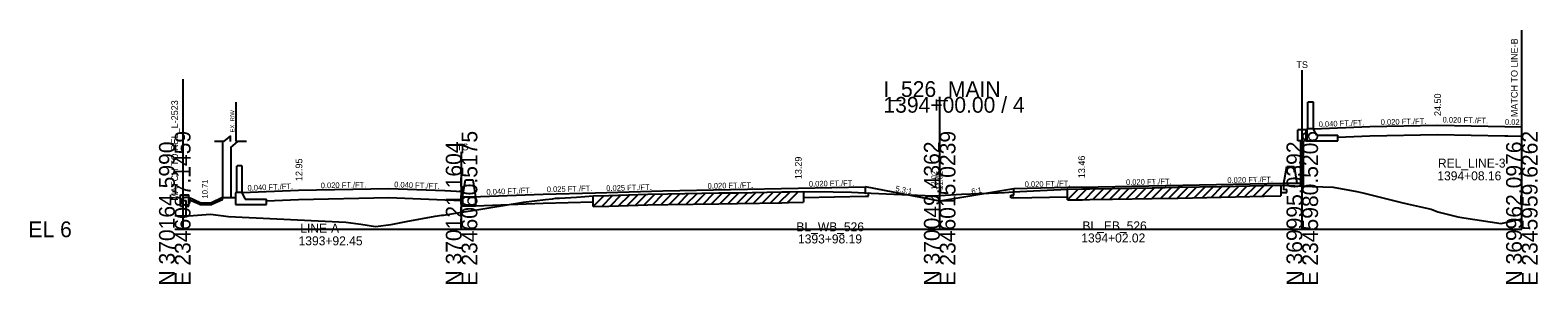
# Model space of a CAD drawing. Extents: x -170 to 2527928, y -10 to 1619750.
# Drawn here: x 1974.3 to 2242.2, y 5990.3 to 6035.4 of the extents above; entities that cross this region are included whole.
import ezdxf

# ---------------------------------------------------------------- set-up
doc = ezdxf.new("R2010")
doc.units = 0
for name, color, linetype in [('Default', 7, 'Continuous'), ('RD_GPK_XS_Cell', 7, 'Continuous'), ('RD_PD_NOISE-WALL-GM', 7, 'Continuous'), ('RD_PD_WallFill', 7, 'Continuous'), ('RD_XS_Base', 7, 'Continuous'), ('RD_XS_EarthShd', 7, 'Continuous'), ('RD_XS_ExGround', 7, 'Continuous'), ('RD_XS_ExPaveRet', 7, 'Continuous'), ('RD_XS_ExRW', 7, 'Continuous'), ('RD_XS_MatchLine', 7, 'Continuous'), ('RD_XS_MedBWall', 7, 'Continuous'), ('RD_XS_Pave', 7, 'Continuous'), ('RD_XS_PaveShd', 7, 'Continuous'), ('RD_XS_TieSlope', 7, 'Continuous'), ('RD_XS_TX_Elev_EX', 7, 'Continuous'), ('RD_XS_TX_Elev_PR', 7, 'Continuous'), ('RD_XS_TX_Slope', 7, 'Continuous'), ('RD_XS_TX_Station', 7, 'Continuous')]:
    doc.layers.add(name, color=color, linetype=linetype)

msp = doc.modelspace()

# ---------------------------------------------------------------- linework, layer by layer
at = {"layer": 'Default'}
for p, q in [((2009.88, 6016.61), (2008.63, 6015.58)), ((2009.88, 6015.58), (2009.88, 6016.61)), ((2008.63, 6015.58), (2007.05, 6015.58)), ((2011.13, 6015.58), (2009.88, 6014.55)), ((2012.72, 6015.58), (2011.13, 6015.58))]:
    msp.add_line(p, q, dxfattribs=at)
at = {"layer": 'RD_GPK_XS_Cell'}
for p, q in [((2135.89, 6000), (2135.89, 6023.52)), ((2000, 6000), (2050.95, 6000)), ((2050.95, 6000), (2135.89, 6000)), ((2135.89, 6000), (2200.3, 6000)), ((2200.3, 6000), (2239.31, 6000))]:
    msp.add_line(p, q, dxfattribs=at)
at = {"layer": 'RD_PD_NOISE-WALL-GM'}
for p, q in [((2008.5, 6015.58), (2008.5, 6005.63)), ((2010, 6005.63), (2010, 6014.66)), ((2197.05, 6008.18), (2197.53, 6011.18)), ((2197.53, 6011.18), (2198.87, 6011.18)), ((2198.87, 6011.18), (2199.36, 6008.18)), ((2051.14, 6005.79), (2051.62, 6008.79)), ((2051.62, 6008.79), (2052.96, 6008.79)), ((2052.96, 6008.79), (2053.45, 6005.79)), ((2051.14, 6005.79), (2053.45, 6005.79))]:
    msp.add_line(p, q, dxfattribs=at)
at = {"layer": 'RD_PD_WallFill'}
for p, q in [((2201.3, 6017.86), (2201.3, 6022.62)), ((2202.3, 6022.62), (2201.3, 6022.62)), ((2202.3, 6017.86), (2202.3, 6022.62)), ((2199.52, 6015.7), (2199.52, 6017.7)), ((2201.02, 6017.7), (2199.52, 6017.7)), ((2201.17, 6017.86), (2201.01, 6017.7)), ((2201.02, 6015.7), (2201.02, 6017.7)), ((2201.09, 6017.7), (2201.02, 6017.7)), ((2201.09, 6017.78), (2201.09, 6015.7)), ((2202.3, 6017.86), (2201.17, 6017.86)), ((2202.3, 6017.86), (2202.3, 6017.7)), ((2202.3, 6017.7), (2202.8, 6016.7)), ((2202.8, 6016.7), (2206.59, 6016.7)), ((2206.59, 6015.7), (2206.59, 6016.7)), ((2239.31, 6001.87), (2239.31, 6018.2)), ((2200.02, 6015.7), (2199.52, 6015.7)), ((2200.02, 6007.7), (2200.02, 6015.7)), ((2200.52, 6007.68), (2200.52, 6015.7)), ((2201.02, 6015.7), (2200.52, 6015.7)), ((2201.02, 6015.7), (2206.59, 6015.7)), ((2201.09, 6015.7), (2201.02, 6015.7)), ((2011.08, 6011.3), (2011, 6011.22)), ((2011, 6006.55), (2011, 6011.22)), ((2011.92, 6011.3), (2011.08, 6011.3)), ((2011.92, 6011.3), (2012, 6011.22)), ((2012, 6006.55), (2012, 6011.22)), ((2197.05, 6008.18), (2200.02, 6008.18)), ((2001, 6006.13), (2002.5, 6006.13)), ((2001, 6004.13), (2001, 6006.13)), ((2001.5, 6002.43), (2001.5, 6005.13)), ((2001.5, 6005.13), (2002, 6005.13)), ((2002, 6002.38), (2002, 6005.13)), ((2002.5, 6004.13), (2002.5, 6006.13)), ((2004.5, 6004.71), (2002.5, 6005.63)), ((2004.43, 6004.38), (2002.5, 6005.26)), ((2008.5, 6005.63), (2006.5, 6004.71)), ((2008.5, 6005.26), (2006.57, 6004.38)), ((2008.5, 6005.26), (2008.5, 6005.63)), ((2010.87, 6006.55), (2010.79, 6006.47)), ((2010.79, 6006.47), (2010.79, 6004.38)), ((2012, 6006.55), (2010.87, 6006.55)), ((2012, 6006.55), (2012, 6006.38)), ((2012, 6006.38), (2012.49, 6005.38)), ((2012.49, 6005.38), (2016.29, 6005.38)), ((2016.29, 6004.38), (2016.29, 6005.38)), ((2051.11, 6006.74), (2051.11, 6005.7)), ((2001, 6004.13), (2001.5, 6004.13)), ((2002, 6004.13), (2002.5, 6004.13)), ((2004.43, 6004.38), (2006.57, 6004.38)), ((2004.5, 6004.71), (2006.5, 6004.71)), ((2010.79, 6004.38), (2016.29, 6004.38))]:
    msp.add_line(p, q, dxfattribs=at)
at = {"layer": 'RD_XS_Base'}
for p, q in [((2206.59, 6016.4), (2212.3, 6016.63)), ((2212.3, 6016.63), (2224.3, 6016.87)), ((2224.3, 6016.87), (2236.3, 6016.63)), ((2236.3, 6016.63), (2236.8, 6016.62)), ((2236.3, 6016.63), (2239.31, 6016.57)), ((2197.05, 6007.04), (2197.05, 6008.18)), ((2016.29, 6005.08), (2022, 6005.31)), ((2022, 6005.31), (2038, 6005.63)), ((2038, 6005.63), (2048, 6005.23)), ((2048, 6005.23), (2051.11, 6005.11)), ((2051.11, 6005.11), (2051.11, 6006.15)), ((2111.68, 6005.67), (2122.72, 6005.89)), ((2122.72, 6006.39), (2122.72, 6007.53)), ((2123.22, 6006.4), (2122.72, 6006.39)), ((2122.72, 6005.89), (2123.22, 6005.9)), ((2123.22, 6005.9), (2123.22, 6006.4)), ((2148.55, 6006.07), (2149.05, 6006.08)), ((2148.55, 6005.57), (2148.55, 6006.07)), ((2149.05, 6005.58), (2148.55, 6005.57)), ((2149.05, 6006.08), (2149.05, 6007.22)), ((2149.05, 6005.58), (2158.59, 6005.77)), ((2196.48, 6006.53), (2197.05, 6006.54)), ((2197.55, 6007.05), (2197.05, 6007.04)), ((2197.05, 6006.54), (2197.55, 6006.55)), ((2197.55, 6006.55), (2197.55, 6007.05)), ((2053.45, 6004.16), (2065.45, 6004.64)), ((2065.45, 6004.64), (2074.34, 6004.86))]:
    msp.add_line(p, q, dxfattribs=at)
at = {"layer": 'RD_XS_EarthShd'}
msp.add_line((2008.5, 6005.63), (2010.79, 6005.63), dxfattribs=at)
at = {"layer": 'RD_XS_ExGround'}
msp.add_lwpolyline([(2000, 6002.44), (2002.5, 6002.41), (2006.37, 6002.69), (2009.53, 6002.26), (2030.38, 6001.26), (2033.05, 6000.92), (2035.68, 6000.51), (2038.44, 6000.84), (2041.11, 6001.36), (2046.26, 6002.31), (2047.42, 6002.5), (2047.71, 6002.5), (2050.95, 6003.03), (2051.75, 6003.16), (2054, 6003.5), (2055.77, 6003.79), (2061.96, 6004.85), (2065.87, 6005.27), (2067.11, 6005.42), (2067.63, 6005.51), (2068.36, 6005.53), (2071.39, 6005.73), (2074.34, 6005.95), (2077.13, 6006.03), (2084.01, 6006.25), (2087.58, 6006.31), (2096.65, 6006.46), (2099.95, 6006.51), (2107.85, 6006.65), (2109, 6006.67), (2111.68, 6006.73), (2116.97, 6006.65), (2120.21, 6006.62), (2123.71, 6006.45), (2127.72, 6006.26), (2134.73, 6005.96), (2135.89, 6006.02), (2139.78, 6006.23), (2146.29, 6006.49), (2147.43, 6006.55), (2148.95, 6006.63), (2158.59, 6007.16), (2161.27, 6007.18), (2162.59, 6007.19), (2166.61, 6007.27), (2173.62, 6007.38), (2178.24, 6007.47), (2185.91, 6007.63), (2193.51, 6007.78), (2196.48, 6007.84), (2197.71, 6007.79), (2200.3, 6007.69), (2205.8, 6007.46), (2209.98, 6006.7), (2211.07, 6006.49), (2217.69, 6004.81), (2218.92, 6004.5), (2218.94, 6004.5), (2223.2, 6003.55), (2224.41, 6003.1), (2227.94, 6002.21), (2228.98, 6002.03), (2235.63, 6001.02), (2239.31, 6001.87)], dxfattribs=at)
at = {"layer": 'RD_XS_ExPaveRet'}
for p, q in [((2191.59, 6005.82), (2193.54, 6007.78)), ((2193.09, 6005.85), (2195.05, 6007.81)), ((2196.48, 6007.84), (2196.48, 6005.92)), ((2074.34, 6004.04), (2076.31, 6006.01)), ((2074.34, 6004.04), (2074.34, 6005.95)), ((2075.84, 6004.08), (2077.81, 6006.05)), ((2077.34, 6004.12), (2079.32, 6006.1)), ((2078.84, 6004.17), (2080.82, 6006.15)), ((2080.34, 6004.22), (2082.32, 6006.19)), ((2081.84, 6004.26), (2083.82, 6006.24)), ((2083.34, 6004.31), (2085.3, 6006.27)), ((2084.84, 6004.34), (2086.79, 6006.29)), ((2086.34, 6004.37), (2088.29, 6006.32)), ((2087.84, 6004.4), (2089.79, 6006.34)), ((2089.34, 6004.42), (2091.29, 6006.37)), ((2090.84, 6004.44), (2092.79, 6006.39)), ((2092.34, 6004.47), (2094.29, 6006.42)), ((2093.84, 6004.49), (2095.79, 6006.44)), ((2095.34, 6004.52), (2097.29, 6006.47)), ((2096.84, 6004.54), (2098.79, 6006.49)), ((2098.34, 6004.57), (2100.29, 6006.52)), ((2099.84, 6004.59), (2101.79, 6006.54)), ((2101.34, 6004.62), (2103.29, 6006.57)), ((2102.84, 6004.64), (2104.79, 6006.59)), ((2104.34, 6004.67), (2106.29, 6006.62)), ((2105.84, 6004.69), (2107.79, 6006.64)), ((2107.34, 6004.72), (2109.3, 6006.68)), ((2108.84, 6004.75), (2110.8, 6006.71)), ((2111.68, 6006.73), (2111.68, 6004.81)), ((2158.59, 6005.24), (2160.52, 6007.17)), ((2158.59, 6005.24), (2158.59, 6007.16)), ((2158.59, 6005.24), (2161.27, 6005.26)), ((2160.09, 6005.25), (2162.02, 6007.19)), ((2161.27, 6005.26), (2162.59, 6005.27)), ((2161.59, 6005.26), (2163.53, 6007.21)), ((2162.59, 6005.27), (2166.61, 6005.35)), ((2163.09, 6005.28), (2165.04, 6007.24)), ((2164.59, 6005.31), (2166.54, 6007.27)), ((2166.09, 6005.34), (2168.04, 6007.29)), ((2166.61, 6005.35), (2173.62, 6005.46)), ((2167.59, 6005.37), (2169.54, 6007.31)), ((2169.09, 6005.39), (2171.04, 6007.34)), ((2170.59, 6005.41), (2172.54, 6007.36)), ((2172.09, 6005.44), (2174.04, 6007.39)), ((2173.59, 6005.46), (2175.54, 6007.42)), ((2173.62, 6005.46), (2178.24, 6005.55)), ((2175.09, 6005.49), (2177.05, 6007.45)), ((2176.59, 6005.52), (2178.55, 6007.48)), ((2178.09, 6005.55), (2180.05, 6007.51)), ((2178.24, 6005.55), (2185.91, 6005.72)), ((2179.59, 6005.58), (2181.55, 6007.54)), ((2181.09, 6005.61), (2183.05, 6007.57)), ((2182.59, 6005.65), (2184.55, 6007.6)), ((2184.09, 6005.68), (2186.05, 6007.64)), ((2185.59, 6005.71), (2187.54, 6007.66)), ((2185.91, 6005.72), (2193.51, 6005.86)), ((2187.09, 6005.74), (2189.04, 6007.69)), ((2188.59, 6005.77), (2190.54, 6007.72)), ((2190.09, 6005.8), (2192.04, 6007.75)), ((2193.51, 6005.86), (2196.48, 6005.92)), ((2074.34, 6004.04), (2077.13, 6004.12)), ((2077.13, 6004.12), (2084.01, 6004.33)), ((2084.01, 6004.33), (2087.58, 6004.39)), ((2087.58, 6004.39), (2096.65, 6004.54)), ((2096.65, 6004.54), (2099.95, 6004.6)), ((2099.95, 6004.6), (2107.85, 6004.73)), ((2107.85, 6004.73), (2109, 6004.75)), ((2109, 6004.75), (2111.68, 6004.81))]:
    msp.add_line(p, q, dxfattribs=at)
at = {"layer": 'RD_XS_ExRW'}
msp.add_line((2010.88, 6015.6), (2010.88, 6022.6), dxfattribs=at)
at = {"layer": 'RD_XS_MatchLine'}
for p, q in [((2239.31, 6000), (2239.31, 6035.39)), ((2001.5, 6000), (2001.5, 6026.65)), ((2200.3, 6000), (2200.3, 6028.27)), ((2050.95, 6000), (2050.95, 6013.78))]:
    msp.add_line(p, q, dxfattribs=at)
at = {"layer": 'RD_XS_MedBWall'}
for p, q in [((2051.11, 6005.79), (2051.11, 6004.16)), ((2053.45, 6005.79), (2053.45, 6004.16)), ((2051.11, 6004.16), (2053.45, 6004.16))]:
    msp.add_line(p, q, dxfattribs=at)
at = {"layer": 'RD_XS_Pave'}
for p, q in [((2212.3, 6018.26), (2224.3, 6018.5)), ((2224.3, 6018.5), (2236.3, 6018.26)), ((2161.05, 6007.46), (2185.05, 6007.94)), ((2022, 6006.95), (2038, 6007.27)), ((2065.45, 6006.27), (2074.72, 6006.51)), ((2074.72, 6006.51), (2086.72, 6006.81)), ((2086.72, 6006.81), (2110.72, 6007.29))]:
    msp.add_line(p, q, dxfattribs=at)
at = {"layer": 'RD_XS_PaveShd'}
for p, q in [((2202.3, 6017.86), (2212.3, 6018.26)), ((2236.3, 6018.26), (2239.31, 6018.2)), ((2185.05, 6007.94), (2197.05, 6008.18)), ((2012, 6006.55), (2022, 6006.95)), ((2038, 6007.27), (2048, 6006.87)), ((2048, 6006.87), (2051.11, 6006.74)), ((2051.11, 6005.7), (2065.45, 6006.27)), ((2110.72, 6007.29), (2122.72, 6007.53)), ((2161.05, 6007.46), (2149.05, 6007.22))]:
    msp.add_line(p, q, dxfattribs=at)
at = {"layer": 'RD_XS_TieSlope'}
for p, q in [((2135.89, 6005.02), (2122.72, 6007.53)), ((2149.05, 6007.22), (2135.89, 6005.02))]:
    msp.add_line(p, q, dxfattribs=at)

# ---------------------------------------------------------------- texts
at = {"layer": 'RD_GPK_XS_Cell'}
for s, p in [('I_526_MAIN', (2125.89, 6023.52)), ('1394+00.00 / 4', (2125.89, 6020.72)), ('EL 6', (1974, 5998.6))]:
    msp.add_text(s, height=2.8, dxfattribs=at).set_placement(p)
for s, p in [('E 2346087.1459', (2002.8, 5990)), ('E 2346060.5175', (2053.75, 5990)), ('E 2346015.0239', (2138.69, 5990)), ('E 2345980.5206', (2203.1, 5990)), ('E 2345959.6262', (2242.11, 5990)), ('N 370164.5990', (2000, 5990)), ('N 370121.1604', (2050.95, 5990)), ('N 370049.4362', (2135.89, 5990)), ('N 369995.0392', (2200.3, 5990)), ('N 369962.0976', (2239.31, 5990))]:
    msp.add_text(s, height=2.8, rotation=90, dxfattribs=at).set_placement(p)
at = {"layer": 'RD_XS_ExRW'}
msp.add_text('EX. R/W ', height=0.75, rotation=90, dxfattribs=at).set_placement((2010.6, 6017.21))
at = {"layer": 'RD_XS_MatchLine'}
for s, p in [('MATCH TO LINE-B', (2238.57, 6019.93)), ('MATCH TO REL_L-2523', (2000.57, 6005.1))]:
    msp.add_text(s, height=1.2, rotation=90, dxfattribs=at).set_placement(p)
for p in [(2199.26, 6028.65), (2050.09, 6014.03)]:
    msp.add_text('TS', height=1.2, dxfattribs=at).set_placement(p)
at = {"layer": 'RD_XS_TX_Elev_EX'}
msp.add_text('12.02', height=1, rotation=90, dxfattribs=at).set_placement((2135.39, 6007.02))
at = {"layer": 'RD_XS_TX_Elev_PR'}
msp.add_text('11.02', height=1, rotation=90, dxfattribs=at).set_placement((2136.39, 6007.02))
at = {"layer": 'RD_XS_TX_Slope'}
for s, rotation, p in [('0.040 FT./FT.', 2.2906, (2203.24, 6018.15)), ('0.020 FT./FT.', 1.1458, (2214.25, 6018.55)), ('0.020 FT./FT.', 358.8542, (2225.22, 6018.98)), ('0.02', 358.8542, (2236.3, 6018.58)), ('10.71', 90, (2005.86, 6005.49)), ('0.040 FT./FT.', 2.2906, (2012.94, 6006.84)), ('0.020 FT./FT.', 1.1458, (2025.94, 6007.28)), ('0.040 FT./FT.', 357.7094, (2038.96, 6007.48)), ('0.025 FT./FT.', 1.4321, (2066.1, 6006.59)), ('0.025 FT./FT.', 1.4321, (2076.66, 6006.8)), ('0.020 FT./FT.', 1.1458, (2094.66, 6007.21)), ('0.020 FT./FT.', 1.1458, (2112.66, 6007.57)), ('0.020 FT./FT.', 1.1458, (2151, 6007.5)), ('0.020 FT./FT.', 1.1458, (2169, 6007.86)), ('0.020 FT./FT.', 1.1458, (2187, 6008.22)), ('0.040 FT./FT.', 2.2906, (2055.39, 6006.12)), ('5.3:1', 349.233, (2127.97, 6006.78)), ('6:1', 9.4623, (2141.6, 6006.23))]:
    msp.add_text(s, height=1, rotation=rotation, dxfattribs=at).set_placement(p)
at = {"layer": 'RD_XS_TX_Station'}
for s, p in [(' 24.50', (2224.96, 6019.68)), (' 12.95', (2022.66, 6008.12)), (' 13.29', (2111.38, 6008.46)), (' 13.46', (2161.71, 6008.63))]:
    msp.add_text(s, height=1.2, rotation=90, dxfattribs=at).set_placement(p)
for s, p in [('REL_LINE-3', (2224.4, 6010.96)), ('1394+08.16', (2224.3, 6008.7)), ('LINE-A', (2022.29, 5999.4)), ('BL_WB_526', (2110.43, 5999.64)), ('BL_EB_526', (2161.25, 5999.81)), ('1393+92.45', (2022, 5997.15)), ('1393+98.19', (2110.72, 5997.49)), ('1394+02.02', (2161.05, 5997.66))]:
    msp.add_text(s, height=1.6, dxfattribs=at).set_placement(p)

doc.saveas('drawing.dxf')
